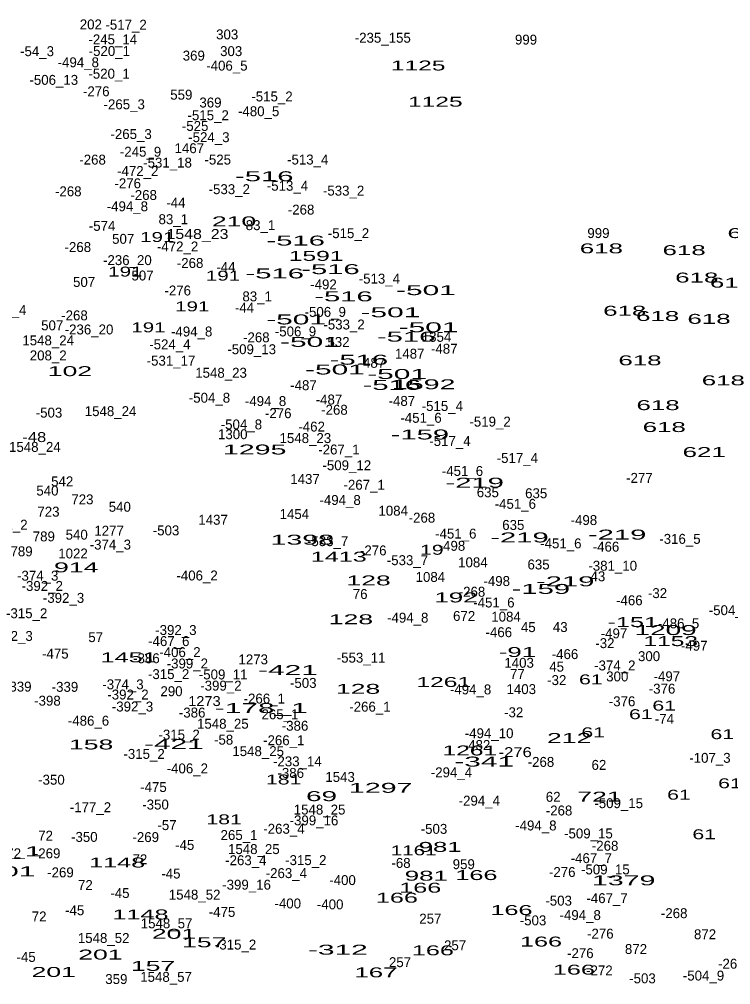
# Model space of a CAD drawing. Extents: x -660434 to -656144, y -997850 to -994016.
# Drawn here: x -658418.1 to -658131.4, y -996475.1 to -996086.1 of the extents above; entities that cross this region are included whole.
import ezdxf
from ezdxf.enums import TextEntityAlignment as Align

# ---------------------------------------------------------------- set-up
doc = ezdxf.new("R2010")
doc.units = 0
doc.header["$LTSCALE"] = 1.6
doc.layers.add('24', color=7, linetype='Continuous')

msp = doc.modelspace()

# ---------------------------------------------------------------- texts
at = {"layer": '24'}
for s, p in [('202', (-658389.281, -996090.11)), ('-517_2', (-658375.072, -996090.23)), ('303', (-658334.321, -996094.14)), ('-245_14', (-658380.444, -996096.14)), ('-235_155', (-658271.605, -996095.49)), ('999', (-658213.863, -996096.23)), ('-54_3', (-658410.967, -996100.9)), ('-520_1', (-658381.83, -996100.83)), ('369', (-658347.788, -996102.67)), ('303', (-658332.721, -996100.88)), ('-494_8', (-658394.336, -996105.37)), ('-406_5', (-658334.436, -996106.72)), ('-520_1', (-658381.93, -996109.96)), ('-506_13', (-658404.215, -996112.46)), ('-276', (-658387.095, -996117.07)), ('559', (-658352.813, -996118.44)), ('-265_3', (-658375.828, -996122.3)), ('369', (-658341.068, -996121.59)), ('-515_2', (-658316.256, -996119.14)), ('-480_5', (-658321.631, -996125.1)), ('-515_2', (-658341.986, -996126.72)), ('-525', (-658347.245, -996131.04)), ('-265_3', (-658373.048, -996134.3)), ('-524_3', (-658341.697, -996135.56)), ('-245_9', (-658369.252, -996141.43)), ('1467', (-658349.595, -996140)), ('-268', (-658388.58, -996144.6)), ('-525', (-658338.125, -996144.58)), ('-513_4', (-658301.86, -996144.57)), ('-472_2', (-658370.372, -996149.2)), ('-531_18', (-658358.359, -996145.81)), ('-268', (-658398.37, -996157.37)), ('-276', (-658374.425, -996154.14)), ('-533_2', (-658333.482, -996156.52)), ('-513_4', (-658310.02, -996155.14)), ('-533_2', (-658287.402, -996157.1)), ('-268', (-658367.99, -996158.86)), ('-494_8', (-658374.556, -996163.42)), ('-44', (-658354.983, -996161.93)), ('-268', (-658304.53, -996164.75)), ('83_1', (-658356.039, -996168.62)), ('-574', (-658384.755, -996171.3)), ('83_1', (-658320.899, -996171.02)), ('507', (-658376.247, -996176.54)), ('-515_2', (-658285.436, -996174.25)), ('999', (-658184.683, -996174.21)), ('-268', (-658394.53, -996179.84)), ('-472_2', (-658354.322, -996179.61)), ('-236_20', (-658374.551, -996185.12)), ('-268', (-658349.27, -996186.27)), ('-44', (-658334.823, -996187.86)), ('507', (-658368.447, -996191.31)), ('507', (-658391.987, -996193.93)), ('-492', (-658295.505, -996194.91)), ('-513_4', (-658272.97, -996192.56)), ('-276', (-658354.265, -996197.36)), ('83_1', (-658322.239, -996199.73)), ('-54_4', (-658422.091, -996205.2)), ('-268', (-658395.87, -996207.39)), ('-44', (-658327.343, -996204.28)), ('-506_9', (-658294.797, -996205.98)), ('507', (-658404.847, -996211.4)), ('-533_2', (-658287.212, -996211.06)), ('-236_20', (-658390.011, -996213.06)), ('-494_8', (-658348.636, -996213.88)), ('-506_9', (-658306.787, -996213.86)), ('1548_24', (-658406.477, -996217.46)), ('-524_4', (-658357.411, -996219.06)), ('-268', (-658322.58, -996216.23)), ('532', (-658289.457, -996218.09)), ('1354', (-658249.944, -996216.03)), ('208_2', (-658406.459, -996223.52)), ('-509_13', (-658324.445, -996221.02)), ('1487', (-658260.76, -996222.81)), ('-487', (-658246.825, -996220.83)), ('-531_17', (-658356.965, -996225.63)), ('-487', (-658276.005, -996226.5)), ('1548_23', (-658336.792, -996230.52)), ('-487', (-658303.565, -996235.52)), ('-504_8', (-658341.461, -996240.57)), ('-494_8', (-658318.856, -996241.93)), ('-487', (-658293.295, -996241.29)), ('-487', (-658263.915, -996241.86)), ('-503', (-658406.139, -996246.57)), ('1548_24', (-658381.317, -996245.98)), ('-276', (-658313.745, -996246.8)), ('-268', (-658291.09, -996245.43)), ('-515_4', (-658247.6, -996243.92)), ('-451_6', (-658256.186, -996248.67)), ('-519_2', (-658228.352, -996250.2)), ('-504_8', (-658328.591, -996251.33)), ('-462', (-658300.285, -996252.21)), ('1300', (-658332.078, -996255.28)), ('1548_23', (-658302.812, -996256.84)), ('-517_4', (-658244.536, -996258.03)), ('1548_24', (-658411.847, -996260.39)), ('-267_1', (-658289.287, -996261.44)), ('-517_4', (-658217.366, -996264.85)), ('-509_12', (-658286.105, -996267.79)), ('-451_6', (-658239.486, -996270.09)), ('1437', (-658302.95, -996273.34)), ('-277', (-658168.185, -996272.88)), ('540', (-658406.785, -996278)), ('542', (-658400.821, -996274.3)), ('-267_1', (-658279.107, -996275.66)), ('723', (-658392.683, -996281.54)), ('-494_8', (-658288.806, -996281.79)), ('635', (-658229.263, -996278.68)), ('635', (-658209.773, -996279.07)), ('540', (-658377.605, -996284.53)), ('-451_6', (-658218.176, -996283.34)), ('723', (-658406.363, -996286.49)), ('1454', (-658307.259, -996287.46)), ('1084', (-658267.408, -996286.1)), ('-268', (-658255.82, -996288.91)), ('-392_2', (-658423.098, -996291.76)), ('1437', (-658340.01, -996289.76)), ('635', (-658218.993, -996291.84)), ('-498', (-658190.545, -996289.88)), ('789', (-658408.238, -996296.47)), ('540', (-658394.985, -996295.77)), ('1277', (-658381.921, -996294.17)), ('-503', (-658358.959, -996294.05)), ('-451_6', (-658242.176, -996295.34)), ('-316_5', (-658151.822, -996297.46)), ('-374_3', (-658381.412, -996299.75)), ('-533_7', (-658293.838, -996298.38)), ('-498', (-658243.725, -996300.25)), ('-451_6', (-658199.836, -996299.28)), ('-466', (-658181.639, -996300.6)), ('789', (-658417.208, -996302.48)), ('1022', (-658396.464, -996303.35)), ('-276', (-658275.445, -996302.12)), ('-533_7', (-658261.668, -996306.05)), ('1084', (-658235.278, -996306.91)), ('635', (-658208.813, -996307.78)), ('-381_10', (-658178.923, -996308.29)), ('-374_3', (-658410.692, -996312.31)), ('-406_2', (-658346.456, -996312.22)), ('1084', (-658252.428, -996312.8)), ('43', (-658184.911, -996312.54)), ('-392_2', (-658408.868, -996316.42)), ('-498', (-658225.675, -996314.46)), ('76', (-658280.718, -996319.69)), ('-268', (-658235.65, -996318.77)), ('-32', (-658160.865, -996319.33)), ('-392_3', (-658400.288, -996321.24)), ('-451_6', (-658226.816, -996323.1)), ('-466', (-658172.229, -996322.21)), ('-315_2', (-658415.146, -996327.43)), ('672', (-658238.818, -996328.53)), ('-504_6', (-658131.886, -996326.2)), ('-494_8', (-658261.546, -996329.23)), ('1084', (-658221.928, -996328.81)), ('-486_5', (-658152.372, -996331.5)), ('-392_3', (-658354.998, -996334.2)), ('-466', (-658224.839, -996335.08)), ('45', (-658212.961, -996333.03)), ('43', (-658200.081, -996333)), ('-497', (-658178.42, -996335.55)), ('-392_3', (-658421.028, -996336.58)), ('57', (-658387.313, -996337.07)), ('-467_6', (-658357.863, -996338.67)), ('-32', (-658182.075, -996339.49)), ('-475', (-658403.595, -996343.71)), ('-406_2', (-658353.366, -996343.11)), ('-466', (-658198.159, -996343.91)), ('-497', (-658146.06, -996340.54)), ('-386', (-658366.88, -996345.57)), ('-399_2', (-658350.383, -996347.68)), ('1273', (-658323.826, -996346.04)), ('-553_11', (-658280.349, -996345.34)), ('1403', (-658216.648, -996347.41)), ('300', (-658164.275, -996344.74)), ('77', (-658217.339, -996351.87)), ('45', (-658201.531, -996348.97)), ('-374_2', (-658178.082, -996348.48)), ('-315_2', (-658357.926, -996351.97)), ('-509_11', (-658335.939, -996352.1)), ('-503', (-658303.659, -996355.52)), ('-32', (-658201.475, -996354.38)), ('300', (-658177.085, -996352.91)), ('-497', (-658157.1, -996352.84)), ('-339', (-658418.54, -996357)), ('-339', (-658399.72, -996357.1)), ('-374_3', (-658376.322, -996356.09)), ('290', (-658356.767, -996358.86)), ('-399_2', (-658336.853, -996356.61)), ('-494_8', (-658236.216, -996358.14)), ('1403', (-658215.788, -996358.02)), ('-376', (-658159.045, -996357.84)), ('-398', (-658406.77, -996362.68)), ('-392_2', (-658374.318, -996360.2)), ('-266_1', (-658319.377, -996361.82)), ('-376', (-658175.155, -996362.93)), ('-392_3', (-658372.488, -996365.03)), ('-386', (-658348.44, -996367.46)), ('-266_1', (-658276.787, -996365.1)), ('-32', (-658218.845, -996367.35)), ('-486_6', (-658390.218, -996370.75)), ('265_1', (-658313.054, -996368.16)), ('-74', (-658158.085, -996369.99)), ('1548_25', (-658336.072, -996371.97)), ('-386', (-658306.97, -996372.78)), ('-315_2', (-658353.696, -996376.36)), ('-58', (-658335.755, -996378.4)), ('-266_1', (-658311.517, -996378.63)), ('-494_10', (-658228.743, -996375.8)), ('1548_25', (-658321.832, -996383.01)), ('-482', (-658233.609, -996380.54)), ('-315_2', (-658367.816, -996384.13)), ('-107_3', (-658139.736, -996385.72)), ('-406_2', (-658350.386, -996389.97)), ('-233_14', (-658306.029, -996387.14)), ('-268', (-658207.85, -996387.35)), ('62', (-658184.493, -996388.56)), ('-350', (-658405.159, -996394.54)), ('-386', (-658308.7, -996391.79)), ('1543', (-658288.814, -996393.41)), ('-294_4', (-658243.926, -996391.55)), ('-475', (-658364.045, -996397.49)), ('62', (-658202.923, -996401.43)), ('-177_2', (-658389.437, -996405.62)), ('-350', (-658363.199, -996404.53)), ('-294_4', (-658232.696, -996402.97)), ('-509_15', (-658176.515, -996403.99)), ('1548_25', (-658297.082, -996406.56)), ('-268', (-658200.56, -996406.94)), ('-57', (-658358.591, -996412.83)), ('-399_16', (-658299.341, -996410.93)), ('-494_8', (-658209.896, -996412.97)), ('72', (-658407.523, -996417.08)), ('-350', (-658391.909, -996417.59)), ('-269', (-658367.155, -996417.66)), ('265_1', (-658329.554, -996416.83)), ('-263_4', (-658311.442, -996414.31)), ('-503', (-658250.969, -996414.34)), ('-509_15', (-658188.715, -996416.19)), ('-45', (-658351.439, -996420.82)), ('-268', (-658181.99, -996421.16)), ('72', (-658420.383, -996424.19)), ('-269', (-658406.895, -996424.19)), ('1548_25', (-658323.572, -996422.5)), ('72', (-658369.503, -996426.59)), ('-263_4', (-658326.802, -996426.98)), ('-315_2', (-658302.626, -996426.94)), ('-68', (-658264.26, -996428.07)), ('959', (-658238.968, -996428.57)), ('-467_7', (-658187.543, -996426.14)), ('-269', (-658401.525, -996431.88)), ('-45', (-658356.999, -996432.35)), ('-263_4', (-658310.472, -996432.18)), ('-276', (-658199.275, -996431.73)), ('-509_15', (-658181.885, -996430.69)), ('72', (-658391.483, -996436.96)), ('-399_16', (-658326.511, -996436.83)), ('-400', (-658287.827, -996434.99)), ('-45', (-658377.549, -996440.22)), ('1548_52', (-658347.442, -996440.85)), ('-400', (-658309.907, -996444.4)), ('-400', (-658292.817, -996444.78)), ('-503', (-658200.719, -996443.27)), ('-467_7', (-658181.203, -996442.27)), ('-45', (-658395.789, -996447.14)), ('-475', (-658336.395, -996447.82)), ('-494_8', (-658192.036, -996449.09)), ('-268', (-658154.15, -996448.33)), ('72', (-658410.113, -996449.64)), ('1548_57', (-658358.747, -996452.42)), ('257', (-658252.433, -996450.52)), ('-503', (-658211.039, -996451.22)), ('-276', (-658183.915, -996456.57)), ('872', (-658141.703, -996456.82)), ('1548_52', (-658384.112, -996458.33)), ('-315_2', (-658330.946, -996460.97)), ('257', (-658242.453, -996461.28)), ('-276', (-658191.975, -996464.45)), ('872', (-658169.543, -996462.77)), ('-45', (-658415.369, -996465.96)), ('257', (-658264.653, -996468.07)), ('-268', (-658131.11, -996468.69)), ('-272', (-658184.301, -996471.41)), ('359', (-658378.993, -996474.88)), ('1548_57', (-658358.957, -996473.99)), ('-503', (-658166.929, -996474.58)), ('-504_9', (-658142.326, -996473.47))]:
    msp.add_text(s, height=4, dxfattribs=at).set_placement(p, align=Align.CENTER)
for s, width, p in [('1125', 1.85, (-658257.344, -996106.67)), ('1125', 1.85, (-658250.434, -996121.27)), ('-516', 2.2, (-658319.375, -996151.3)), ('210', 2, (-658331.564, -996169.5)), ('191', 1.55, (-658362.519, -996175.8)), ('1548_23', 1.2, (-658346.299, -996174.58)), ('618', 1.95, (-658123.973, -996174.22)), ('-516', 2.2, (-658306.705, -996177.23)), ('618', 1.95, (-658183.493, -996180.37)), ('1591', 1.85, (-658298.479, -996183.4)), ('618', 1.95, (-658150.133, -996181.09)), ('191', 1.55, (-658375.379, -996189.73)), ('191', 1.55, (-658336.019, -996191.36)), ('-516', 2.2, (-658315.155, -996190.48)), ('-516', 2.2, (-658292.695, -996188.75)), ('618', 1.95, (-658145.043, -996192.14)), ('618', 1.95, (-658131.073, -996194.2)), ('-516', 2.2, (-658287.455, -996199.72)), ('-501', 2.25, (-658254.217, -996197.21)), ('191', 1.55, (-658348.409, -996203.75)), ('-501', 2.25, (-658268.527, -996206.13)), ('618', 1.95, (-658174.083, -996205.53)), ('618', 1.95, (-658160.833, -996207.64)), ('-501', 2.25, (-658306.547, -996209.02)), ('618', 1.95, (-658140.103, -996208.79)), ('191', 1.55, (-658366.069, -996212.2)), ('-501', 2.25, (-658253.167, -996212.17)), ('-501', 2.25, (-658300.977, -996218.06)), ('-516', 2.2, (-658262.205, -996215.95)), ('-516', 2.2, (-658281.215, -996225.26)), ('618', 1.95, (-658167.943, -996225.5)), ('102', 2, (-658397.704, -996229.86)), ('-501', 2.25, (-658290.897, -996229.19)), ('-501', 2.25, (-658265.837, -996231.01)), ('1592', 2.15, (-658255.113, -996235.15)), ('618', 1.95, (-658134.343, -996233.57)), ('-516', 2.2, (-658267.965, -996235.44)), ('618', 1.95, (-658160.643, -996243.56)), ('618', 1.95, (-658158.153, -996252.4)), ('-48', 1.25, (-658412.09, -996256.44)), ('-159', 2.2, (-658256.665, -996255.39)), ('1295', 2.15, (-658323.243, -996261.44)), ('621', 1.95, (-658142.053, -996262.48)), ('-219', 2.2, (-658234.555, -996274.8)), ('-219', 2.2, (-658216.505, -996296.89)), ('-219', 2.2, (-658177.145, -996295.73)), ('1398', 2.15, (-658304.053, -996297.78)), ('1413', 1.9, (-658289.369, -996304.64)), ('19', 1.6, (-658251.833, -996301.86)), ('914', 2, (-658395.178, -996308.96)), ('128', 2, (-658277.327, -996314.21)), ('-219', 2.2, (-658198.075, -996314.56)), ('-159', 2.2, (-658207.895, -996317.63)), ('192', 1.95, (-658242.103, -996321.07)), ('128', 2, (-658284.437, -996329.86)), ('-151', 1.9, (-658170.847, -996331)), ('1209', 2.1, (-658157.599, -996334.22)), ('1153', 1.85, (-658155.554, -996338.67)), ('-91', 1.95, (-658217.335, -996343.08)), ('1451', 1.9, (-658374.059, -996345.22)), ('-421', 2.25, (-658309.826, -996350.35)), ('1261', 1.85, (-658247.029, -996355.15)), ('61', 1.6, (-658187.753, -996354.1)), ('128', 2, (-658281.557, -996357.91)), ('1273', 1.1, (-658343.5, -996362.84)), ('-178_1', 2.25, (-658320.573, -996365.65)), ('61', 1.6, (-658158.183, -996364.65)), ('61', 1.6, (-658167.593, -996368.12)), ('212', 2, (-658196.477, -996377.71)), ('61', 1.6, (-658186.793, -996375.42)), ('61', 1.6, (-658134.753, -996376.17)), ('158', 2, (-658389.157, -996380.33)), ('-421', 2.25, (-658355.816, -996380.13)), ('1261', 1.85, (-658236.529, -996382.75)), ('-276', 1.25, (-658218.23, -996383.42)), ('-341', 2.25, (-658230.746, -996387.22)), ('181', 1.6, (-658311.554, -996394.45)), ('1297', 2.15, (-658272.437, -996397.8)), ('61', 1.6, (-658131.683, -996395.96)), ('69', 2.1, (-658296.291, -996401.15)), ('721', 2, (-658184.273, -996401.34)), ('61', 1.6, (-658152.233, -996400.57)), ('181', 1.6, (-658335.554, -996410.49)), ('61', 1.6, (-658142.053, -996416.51)), ('981', 1.95, (-658248.493, -996421.61)), ('-177_1', 2.25, (-658427.967, -996423.39)), ('1161', 1.55, (-658259.155, -996423)), ('1148', 1.9, (-658378.679, -996427.9)), ('-201', 2.25, (-658423.707, -996431.46)), ('981', 1.95, (-658254.053, -996433.23)), ('166', 1.9, (-658233.857, -996432.97)), ('1379', 2.15, (-658174.507, -996435.09)), ('166', 1.9, (-658256.507, -996438.05)), ('166', 1.9, (-658265.917, -996442.09)), ('1148', 1.9, (-658369.269, -996448.84)), ('166', 1.9, (-658219.737, -996447.08)), ('201', 2, (-658355.764, -996456.65)), ('157', 2, (-658343.563, -996460.07)), ('166', 1.9, (-658207.827, -996459.76)), ('-312', 2.25, (-658289.701, -996463.04)), ('166', 1.9, (-658251.417, -996463.31)), ('201', 2, (-658385.424, -996465)), ('201', 2, (-658404.244, -996472.01)), ('157', 2, (-658364.203, -996469.58)), ('167', 1.95, (-658274.357, -996472.19)), ('166', 1.9, (-658194.587, -996471.08))]:
    msp.add_text(s, height=4, dxfattribs=dict(at, width=width)).set_placement(p, align=Align.CENTER)

doc.saveas('drawing.dxf')
